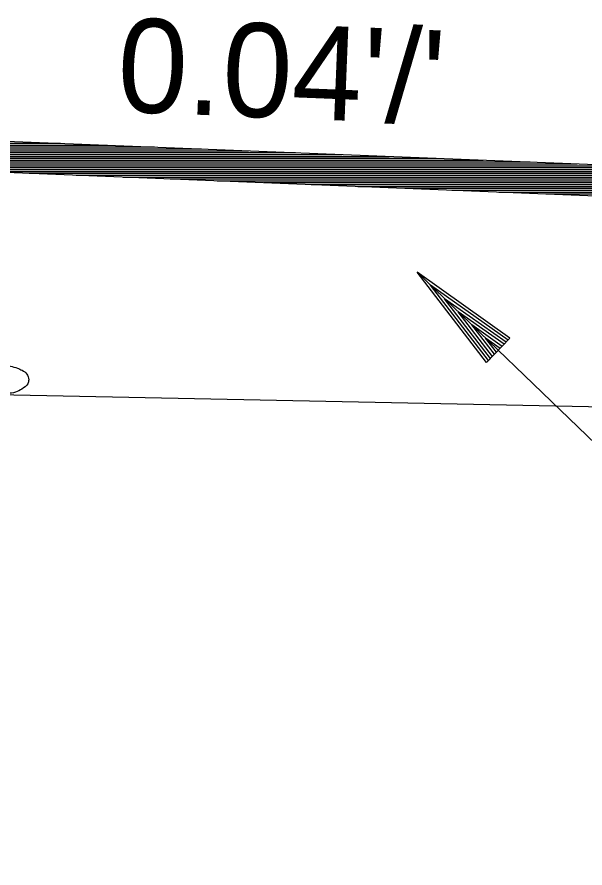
# Model space of a CAD drawing. Extents: x 60325 to 61047, y 53669 to 53767.
# Drawn here: x 60384.437 to 60387.461, y 53685.999 to 53690.53 of the extents above; entities that cross this region are included whole.
import ezdxf

# ---------------------------------------------------------------- set-up
doc = ezdxf.new("R2010")
doc.units = 0
doc.layers.add('R_Border Prem', color=7, linetype='Continuous')

msp = doc.modelspace()

# ---------------------------------------------------------------- linework, layer by layer
at = {"layer": 'R_Border Prem'}
for p, q in [((60381.2467, 53689.9951), (60389.2467, 53689.6751)), ((60381.2467, 53689.8582), (60384.6688, 53689.8582)), ((60381.2467, 53689.8482), (60384.9188, 53689.8482)), ((60381.2467, 53689.8382), (60385.1688, 53689.8382)), ((60381.2467, 53689.8284), (60389.2467, 53689.5084)), ((60381.2523, 53689.8282), (60385.4188, 53689.8282)), ((60381.5023, 53689.8182), (60385.6688, 53689.8182)), ((60381.7523, 53689.8082), (60385.9188, 53689.8082)), ((60382.0023, 53689.7982), (60386.1688, 53689.7982)), ((60382.2523, 53689.7882), (60386.4188, 53689.7882)), ((60382.5023, 53689.7782), (60386.6688, 53689.7782)), ((60382.7523, 53689.7682), (60386.9188, 53689.7682)), ((60383.0023, 53689.7582), (60387.1688, 53689.7582)), ((60383.2523, 53689.7482), (60387.4188, 53689.7482)), ((60383.5023, 53689.7382), (60387.6688, 53689.7382)), ((60383.7523, 53689.7282), (60387.9188, 53689.7282)), ((60384.0023, 53689.7182), (60388.1688, 53689.7182)), ((60384.2523, 53689.7082), (60388.4188, 53689.7082)), ((60384.5023, 53689.6982), (60388.6688, 53689.6982)), ((60384.7523, 53689.6882), (60388.9188, 53689.6882)), ((60385.0023, 53689.6782), (60389.1688, 53689.6782)), ((60385.2523, 53689.6682), (60389.2467, 53689.6682)), ((60385.5023, 53689.6582), (60389.2467, 53689.6582)), ((60385.7523, 53689.6482), (60389.2467, 53689.6482)), ((60386.0023, 53689.6382), (60389.2467, 53689.6382)), ((60386.2523, 53689.6282), (60389.2467, 53689.6282)), ((60386.5023, 53689.6182), (60389.2467, 53689.6182)), ((60386.7523, 53689.6082), (60389.2467, 53689.6082)), ((60387.0023, 53689.5982), (60389.2467, 53689.5982)), ((60387.2523, 53689.5882), (60389.2467, 53689.5882)), ((60389.86, 53685.9994), (60386.5667, 53689.1716)), ((60386.9364, 53688.6905), (60386.5667, 53689.1716)), ((60387.0613, 53688.8202), (60386.5667, 53689.1716)), ((60355.2467, 53689.1017), (60397.7927, 53688.2507)), ((60386.9468, 53688.7013), (60386.6389, 53689.1021)), ((60387.0509, 53688.8094), (60386.6389, 53689.1021)), ((60387.0403, 53688.7983), (60386.7132, 53689.0305)), ((60386.9574, 53688.7123), (60386.7132, 53689.0305)), ((60386.9679, 53688.7232), (60386.7852, 53688.9612)), ((60387.0299, 53688.7875), (60386.7852, 53688.9612)), ((60387.0193, 53688.7765), (60386.8584, 53688.8906)), ((60386.9787, 53688.7344), (60386.8584, 53688.8906)), ((60387.0086, 53688.7655), (60386.9306, 53688.8211)), ((60386.9891, 53688.7452), (60386.9306, 53688.8211)), ((60386.9364, 53688.6905), (60387.0613, 53688.8202))]:
    msp.add_line(p, q, dxfattribs=at)
msp.add_spline([(60384.3432, 53688.6779), (60384.2882, 53688.6716), (60384.2244, 53688.6491), (60384.1919, 53688.6179), (60384.1869, 53688.5991), (60384.2044, 53688.5654), (60384.2232, 53688.5504), (60384.2619, 53688.5329), (60384.3157, 53688.5216), (60384.3432, 53688.5216), (60384.3844, 53688.5254), (60384.4294, 53688.5329), (60384.4632, 53688.5491), (60384.4944, 53688.5779), (60384.4994, 53688.5991), (60384.4894, 53688.6291), (60384.4644, 53688.6491), (60384.4394, 53688.6604), (60384.4019, 53688.6716), (60384.3782, 53688.6766), (60384.3432, 53688.6779)], degree=3, dxfattribs=at)

# ---------------------------------------------------------------- texts
msp.add_text("0.04'/'", height=0.5, rotation=357.7094, dxfattribs=at).set_placement((60384.9647, 53690.0272))

doc.saveas('drawing.dxf')
